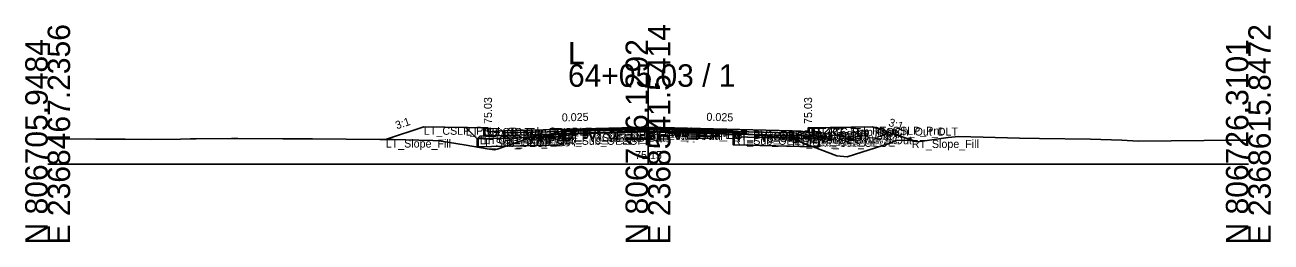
# Model space of a CAD drawing. Extents: x -26 to 8153, y -10 to 9520.
# Drawn here: x 5997.2 to 6152.8, y 4490.3 to 4517.4 of the extents above; entities that cross this region are included whole.
import ezdxf

# ---------------------------------------------------------------- set-up
doc = ezdxf.new("R2010")
doc.units = 0
for name, color, linetype in [('Exist CMT Pavement', 7, 'Continuous'), ('Exist Cross Section Cell', 7, 'Continuous'), ('Exist XS Center Line Elevation Label', 7, 'Continuous'), ('Exist XS Ground Line', 7, 'Continuous'), ('Prop CMT Conc Surface', 7, 'Continuous'), ('Prop CMT Concrete Structures', 7, 'Continuous'), ('Prop CMT Pvmt Course 1', 7, 'Continuous'), ('Prop CMT Pvmt Course 1 CG', 7, 'Continuous'), ('Prop CMT Pvmt Course 1 Wedge', 7, 'Continuous'), ('Prop CMT Pvmt Course 2', 7, 'Continuous'), ('Prop CMT Pvmt Course 2 Wedge', 7, 'Continuous'), ('Prop CMT Pvmt Course 3', 7, 'Continuous'), ('Prop CMT Pvmt Course 3 Wedge', 7, 'Continuous'), ('Prop CMT Pvmt Surface', 7, 'Continuous'), ('Prop CMT Pvmt Wedge Surface 1', 7, 'Continuous'), ('Prop CMT Pvmt Wedge Surface 2', 7, 'Continuous'), ('Prop CMT Pvmt Wedge Surface 3', 7, 'Continuous'), ('Prop CMT Shallow Undercut', 7, 'Continuous'), ('Prop CMT Shallow Undercut Boundary', 7, 'Continuous'), ('Prop CMT Slope Grass', 7, 'Continuous'), ('Prop CMT Subgrade Earthwork', 7, 'Continuous'), ('Prop XS Earthwork Shape', 7, 'Continuous'), ('Prop XS Hydro Elevations', 7, 'Continuous'), ('Prop XS SE Text', 7, 'Continuous'), ('Prop XS Side Slope Text', 7, 'Continuous'), ('Prop XS Subgrade Earthwork', 7, 'Continuous'), ('Scratch_Level_2', 7, 'Continuous'), ('Scratch_Level_6', 7, 'Continuous')]:
    doc.layers.add(name, color=color, linetype=linetype)

msp = doc.modelspace()

# ---------------------------------------------------------------- linework, layer by layer
at = {"layer": 'Exist CMT Pavement'}
for p, q in [((6064.41, 4503.82), (6069.36, 4503.96)), ((6069.36, 4503.96), (6074.69, 4504.16)), ((6074.69, 4504.16), (6075, 4504.15)), ((6075, 4504.15), (6080.34, 4504.06)), ((6080.34, 4504.06), (6085.62, 4503.97))]:
    msp.add_line(p, q, dxfattribs=at)
at = {"layer": 'Exist Cross Section Cell'}
for p, q in [((6075, 4500), (6075, 4512.47)), ((6000, 4500), (6075, 4500)), ((6075, 4500), (6150, 4500))]:
    msp.add_line(p, q, dxfattribs=at)
at = {"layer": 'Exist XS Ground Line'}
for p, q in [((6064.41, 4503.82), (6069.36, 4503.96)), ((6069.36, 4503.96), (6074.69, 4504.16)), ((6074.69, 4504.16), (6075, 4504.15)), ((6075, 4504.15), (6080.34, 4504.06)), ((6080.34, 4504.06), (6085.62, 4503.97)), ((6085.62, 4503.97), (6091.12, 4503.39)), ((6000, 4503.18), (6006, 4503.13)), ((6006, 4503.13), (6009.67, 4503.13)), ((6009.67, 4503.13), (6012.89, 4503.11)), ((6012.89, 4503.11), (6016.59, 4503.15)), ((6016.59, 4503.15), (6017.83, 4503.16)), ((6017.83, 4503.16), (6018.55, 4503.16)), ((6018.55, 4503.16), (6022.98, 4503.21)), ((6022.98, 4503.21), (6023.75, 4503.21)), ((6023.75, 4503.21), (6029.36, 4503.18)), ((6029.36, 4503.18), (6032.63, 4503.17)), ((6032.63, 4503.17), (6033.08, 4503.17)), ((6033.08, 4503.17), (6041.51, 4503.09)), ((6041.51, 4503.09), (6043.17, 4503.08)), ((6043.17, 4503.08), (6046.36, 4503)), ((6046.36, 4503), (6048.13, 4502.95)), ((6048.13, 4502.95), (6048.91, 4502.93)), ((6048.91, 4502.93), (6052.3, 4502.37)), ((6052.3, 4502.37), (6054.91, 4501.94)), ((6056.16, 4501.89), (6060.25, 4503.28)), ((6060.25, 4503.28), (6061.9, 4503.48)), ((6061.9, 4503.48), (6064.41, 4503.82)), ((6091.12, 4503.39), (6092.77, 4503.27)), ((6092.77, 4503.27), (6093.9, 4502.83)), ((6093.9, 4502.83), (6098.6, 4501.07)), ((6099.89, 4500.92), (6105.24, 4502.65)), ((6105.24, 4502.65), (6105.99, 4502.95)), ((6105.99, 4502.95), (6107.52, 4503.03)), ((6107.52, 4503.03), (6108.72, 4502.81)), ((6108.72, 4502.81), (6112.48, 4503.36)), ((6112.48, 4503.36), (6113.83, 4503.45)), ((6113.83, 4503.45), (6121.41, 4503.27)), ((6121.41, 4503.27), (6123.92, 4503.2)), ((6123.92, 4503.2), (6130.28, 4503.13)), ((6130.28, 4503.13), (6134.18, 4503.01)), ((6134.18, 4503.01), (6136.22, 4502.88)), ((6136.22, 4502.88), (6144.46, 4502.96)), ((6144.46, 4502.96), (6147.16, 4502.99)), ((6147.16, 4502.99), (6150, 4503.01)), ((6054.91, 4501.94), (6055.84, 4501.79)), ((6055.84, 4501.79), (6056.16, 4501.89)), ((6098.6, 4501.07), (6099.89, 4500.92))]:
    msp.add_line(p, q, dxfattribs=at)
at = {"layer": 'Prop CMT Conc Surface'}
for points in [[(6055, 4504.03), (6055, 4504.53), (6054.5, 4504.53)], [(6057, 4504.16), (6055, 4504.03)], [(6093, 4504.16), (6095, 4504.03)], [(6095, 4504.03), (6095, 4504.53), (6095.5, 4504.53)]]:
    msp.add_lwpolyline(points, dxfattribs=at)
at = {"layer": 'Prop CMT Concrete Structures'}
for points in [[(6057, 4504.16), (6055, 4504.03), (6055, 4504.53), (6054.5, 4504.53)], [(6054.5, 4504.53), (6054.5, 4503.52), (6057, 4503.58)], [(6057, 4503.58), (6057, 4504.16)], [(6093, 4504.16), (6095, 4504.03), (6095, 4504.53), (6095.5, 4504.53)], [(6095.5, 4504.53), (6095.5, 4503.52), (6093, 4503.58)], [(6093, 4503.58), (6093, 4504.16)]]:
    msp.add_lwpolyline(points, dxfattribs=at)
at = {"layer": 'Prop CMT Pvmt Course 1'}
for points in [[(6075, 4504.61), (6057, 4504.16)], [(6057, 4504.16), (6057, 4503.91)], [(6057, 4503.91), (6064.41, 4504.1)], [(6064.41, 4504.22), (6075, 4504.49)], [(6064.41, 4504.1), (6064.41, 4504.22)], [(6075, 4504.36), (6075, 4504.61)], [(6075, 4504.61), (6093, 4504.16)], [(6075, 4504.36), (6075, 4504.61)], [(6075, 4504.49), (6075, 4504.36), (6075, 4504.36)], [(6085.62, 4504.22), (6075, 4504.49)], [(6075, 4504.49), (6075, 4504.36), (6075, 4504.36)], [(6085.62, 4504.1), (6085.62, 4504.22)], [(6093, 4503.91), (6085.62, 4504.1)], [(6093, 4504.16), (6093, 4503.91)]]:
    msp.add_lwpolyline(points, dxfattribs=at)
at = {"layer": 'Prop CMT Pvmt Course 1 CG'}
for points in [[(6057, 4503.58), (6054, 4503.5), (6053.66, 4503.17)], [(6053.66, 4503.17), (6057, 4503.25)], [(6057, 4503.25), (6057, 4503.58)], [(6093, 4503.58), (6096, 4503.5), (6096.34, 4503.17)], [(6093, 4503.25), (6093, 4503.58)], [(6096.34, 4503.17), (6093, 4503.25)]]:
    msp.add_lwpolyline(points, dxfattribs=at)
at = {"layer": 'Prop CMT Pvmt Course 1 Wedge'}
for points in [[(6075, 4504.49), (6064.41, 4504.22)], [(6075, 4504.49), (6085.62, 4504.22)]]:
    msp.add_lwpolyline(points, dxfattribs=at)
at = {"layer": 'Prop CMT Pvmt Course 2'}
for points in [[(6064.41, 4504.1), (6057, 4503.91)], [(6057, 4503.91), (6057, 4503.58)], [(6064.41, 4503.77), (6064.41, 4504.1)], [(6085.62, 4503.77), (6085.62, 4504.1)], [(6085.62, 4504.1), (6093, 4503.91)], [(6093, 4503.91), (6093, 4503.58)], [(6057, 4503.58), (6064.41, 4503.77)], [(6093, 4503.58), (6085.62, 4503.77)]]:
    msp.add_lwpolyline(points, dxfattribs=at)
at = {"layer": 'Prop CMT Pvmt Course 2 Wedge'}
for points in [[(6075, 4504.36), (6064.41, 4504.1)], [(6075, 4504.36), (6085.62, 4504.1)]]:
    msp.add_lwpolyline(points, dxfattribs=at)
at = {"layer": 'Prop CMT Pvmt Course 3'}
for points in [[(6064.41, 4503.77), (6057, 4503.58)], [(6057, 4503.58), (6057, 4503.25)], [(6057, 4503.25), (6064.41, 4503.43)], [(6064.41, 4503.43), (6064.41, 4503.77)], [(6085.62, 4503.77), (6093, 4503.58)], [(6085.62, 4503.43), (6085.62, 4503.77)], [(6093, 4503.25), (6085.62, 4503.43)], [(6093, 4503.58), (6093, 4503.25)]]:
    msp.add_lwpolyline(points, dxfattribs=at)
at = {"layer": 'Prop CMT Pvmt Course 3 Wedge'}
for points in [[(6075, 4504.03), (6064.41, 4503.77)], [(6075, 4504.03), (6085.62, 4503.77)]]:
    msp.add_lwpolyline(points, dxfattribs=at)
at = {"layer": 'Prop CMT Pvmt Surface'}
for points in [[(6075, 4504.61), (6057, 4504.16)], [(6075, 4504.61), (6093, 4504.16)]]:
    msp.add_lwpolyline(points, dxfattribs=at)
at = {"layer": 'Prop CMT Pvmt Wedge Surface 1'}
for points in [[(6057, 4503.91), (6057, 4504.16)], [(6064.41, 4504.1), (6057, 4503.91)], [(6075, 4504.49), (6064.41, 4504.22)], [(6064.41, 4504.22), (6064.41, 4504.1)], [(6075, 4504.49), (6085.62, 4504.22)], [(6085.62, 4504.22), (6085.62, 4504.1)], [(6085.62, 4504.1), (6093, 4503.91)], [(6093, 4503.91), (6093, 4504.16)]]:
    msp.add_lwpolyline(points, dxfattribs=at)
at = {"layer": 'Prop CMT Pvmt Wedge Surface 2'}
for points in [[(6075, 4504.36), (6057, 4503.91)], [(6057, 4503.91), (6057, 4504.16)], [(6075, 4504.36), (6093, 4503.91)], [(6093, 4503.91), (6093, 4504.16)]]:
    msp.add_lwpolyline(points, dxfattribs=at)
at = {"layer": 'Prop CMT Pvmt Wedge Surface 3'}
for points in [[(6057, 4503.58), (6057, 4504.16)], [(6075, 4504.03), (6057, 4503.58)], [(6075, 4504.03), (6093, 4503.58)], [(6093, 4503.58), (6093, 4504.16)]]:
    msp.add_lwpolyline(points, dxfattribs=at)
at = {"layer": 'Prop CMT Shallow Undercut'}
for points in [[(6060.8, 4503.34), (6064.41, 4503.43), (6064.41, 4502.43), (6057.24, 4502.26), (6060.25, 4503.28)], [(6093.9, 4502.83), (6095.62, 4502.18), (6085.62, 4502.43), (6085.62, 4503.43), (6092.8, 4503.25)]]:
    msp.add_lwpolyline(points, close=True, dxfattribs=at)
at = {"layer": 'Prop CMT Shallow Undercut Boundary'}
for p, q in [((6053.66, 4503.17), (6053.66, 4502.17)), ((6053.66, 4502.17), (6064.41, 4502.43)), ((6064.41, 4503.43), (6064.41, 4502.43)), ((6085.62, 4503.43), (6085.62, 4502.43)), ((6085.62, 4502.43), (6096.34, 4502.17)), ((6096.34, 4503.17), (6096.34, 4502.17))]:
    msp.add_line(p, q, dxfattribs=at)
at = {"layer": 'Prop CMT Slope Grass'}
for points in [[(6054.5, 4504.53), (6047, 4504.68), (6042.21, 4503.09)], [(6095.5, 4504.53), (6103, 4504.68), (6108.52, 4502.84)]]:
    msp.add_lwpolyline(points, dxfattribs=at)
at = {"layer": 'Prop CMT Subgrade Earthwork'}
for points in [[(6057, 4503.25), (6053.66, 4503.17), (6052.25, 4504.58)], [(6085.62, 4503.43), (6085.61, 4503.98)], [(6093, 4503.25), (6096.34, 4503.17), (6097.75, 4504.58)], [(6064.41, 4503.43), (6057, 4503.25)], [(6064.41, 4503.43), (6064.42, 4503.82)], [(6085.62, 4503.43), (6093, 4503.25)]]:
    msp.add_lwpolyline(points, dxfattribs=at)
at = {"layer": 'Prop XS Earthwork Shape'}
for points in [[(6048.13, 4502.95), (6048.91, 4502.93), (6052.3, 4502.37), (6054.91, 4501.94), (6055.84, 4501.79), (6056.16, 4501.89), (6057.24, 4502.26), (6053.66, 4502.17), (6053.66, 4503.17), (6052.25, 4504.58), (6047, 4504.68), (6042.21, 4503.09), (6043.17, 4503.08), (6046.36, 4503)], [(6085.62, 4503.43), (6092.8, 4503.25), (6092.77, 4503.27), (6091.12, 4503.39), (6085.62, 4503.97), (6085.61, 4503.98)], [(6103, 4504.68), (6108.52, 4502.84), (6107.52, 4503.03), (6105.99, 4502.95), (6105.24, 4502.65), (6099.89, 4500.92), (6098.6, 4501.07), (6095.62, 4502.18), (6096.34, 4502.17), (6096.34, 4503.17), (6097.75, 4504.58)], [(6057.24, 4502.26), (6060.25, 4503.28), (6060.8, 4503.34), (6057, 4503.25), (6053.66, 4503.17), (6053.66, 4502.17)], [(6057.24, 4502.26), (6060.25, 4503.28), (6060.8, 4503.34), (6064.41, 4503.43), (6064.41, 4502.43)], [(6064.41, 4503.82), (6064.42, 4503.82), (6064.41, 4503.43), (6060.8, 4503.34), (6061.9, 4503.48)], [(6085.62, 4502.43), (6095.62, 4502.18), (6093.9, 4502.83), (6092.8, 4503.25), (6085.62, 4503.43)], [(6093.9, 4502.83), (6095.62, 4502.18), (6096.34, 4502.17), (6096.34, 4503.17), (6093, 4503.25), (6092.8, 4503.25)]]:
    msp.add_lwpolyline(points, close=True, dxfattribs=at)
at = {"layer": 'Prop XS Subgrade Earthwork'}
for p, q in [((6053.66, 4503.17), (6064.41, 4503.43)), ((6085.62, 4503.43), (6096.34, 4503.17))]:
    msp.add_line(p, q, dxfattribs=at)
at = {"layer": 'Scratch_Level_6'}
for points in [[(6060.8, 4503.34), (6064.41, 4503.43), (6064.41, 4502.43), (6057.24, 4502.26), (6060.25, 4503.28)], [(6093.9, 4502.83), (6095.62, 4502.18), (6085.62, 4502.43), (6085.62, 4503.43), (6092.8, 4503.25)]]:
    msp.add_lwpolyline(points, close=True, dxfattribs=at)

# ---------------------------------------------------------------- texts
at = {"layer": 'Exist Cross Section Cell'}
for s, p in [('E 2368467.2356', (6002.8, 4490)), ('E 2368541.5414', (6077.8, 4490)), ('E 2368615.8472', (6152.8, 4490)), ('N 806705.9484', (6000, 4490)), ('N 806716.1292', (6075, 4490)), ('N 806726.3101', (6150, 4490))]:
    msp.add_text(s, height=2.8, rotation=90, dxfattribs=at).set_placement(p)
for s, p in [('L', (6065, 4512.47)), ('64+05.03 / 1', (6065, 4509.67))]:
    msp.add_text(s, height=2.8, dxfattribs=at).set_placement(p)
at = {"layer": 'Exist XS Center Line Elevation Label'}
msp.add_text('75.15', height=1, dxfattribs=at).set_placement((6073.39, 4500.65))
at = {"layer": 'Prop XS Hydro Elevations'}
for p in [(6055.5, 4505.03), (6095.5, 4505.03)]:
    msp.add_text('75.03', height=1, rotation=90, dxfattribs=at).set_placement(p)
at = {"layer": 'Prop XS SE Text'}
for rotation, p in [(1.4321, (6064.24, 4505.34)), (358.5679, (6082.29, 4505.43))]:
    msp.add_text('0.025', height=1, rotation=rotation, dxfattribs=at).set_placement(p)
at = {"layer": 'Prop XS Side Slope Text'}
for rotation, p in [(18.4349, (6043.62, 4504.35)), (341.565, (6104.96, 4504.82))]:
    msp.add_text('3:1', height=1, rotation=rotation, dxfattribs=at).set_placement(p)
at = {"layer": 'Scratch_Level_2'}
for s, p in [('LT_CSLP_Pnt', (6047, 4503.68)), ('LT_Sub_Trench_Out_DLT', (6052.25, 4503.58)), ('LT_CG_Top_BOC', (6054.5, 4503.53)), ('LT_CG_Top_Face', (6055, 4503.53)), ('LT_CG_Top_Gut', (6055, 4503.03)), ('LT_PV1_OEOT', (6057, 4503.16)), ('LT_PV2_OEOT', (6057, 4502.91)), ('LT_PV1_OEEOP', (6064.41, 4503.22)), ('LT_PV2_OEEOP', (6064.41, 4503.1)), ('LT_PV_Sub_Tie_Out', (6064.42, 4502.82)), ('PV1_PGL', (6075, 4503.61)), ('RT_PV1_IEEOP', (6075, 4503.49)), ('LT_PV1_IEEOP', (6075, 4503.49)), ('RT_PV2_IEEOP', (6075, 4503.36)), ('LT_PV2_IEEOP', (6075, 4503.36)), ('PV2_PGL', (6075, 4503.36)), ('RT_PV_IEEOP_EG', (6075, 4503.15)), ('LT_PV_IEEOP_EG', (6075, 4503.15)), ('RT_PV3_IEEOP', (6075, 4503.03)), ('LT_PV3_IEEOP', (6075, 4503.03)), ('RT_PV_Sub_Tie_Out', (6085.61, 4502.98)), ('RT_PV1_OEEOP', (6085.62, 4503.22)), ('RT_PV2_OEEOP', (6085.62, 4503.1)), ('RT_PV_OEEOP_EG', (6085.62, 4502.97)), ('RT_PV1_OEOT', (6093, 4503.16)), ('RT_PV2_OEOT', (6093, 4502.91)), ('RT_CG_Top_Face', (6095, 4503.53)), ('RT_CG_Top_Gut', (6095, 4503.03)), ('RT_CG_Top_BOC', (6095.5, 4503.53)), ('RT_Sub_Trench_Out_DLT', (6097.75, 4503.58)), ('RT_CSLP_Pnt', (6103, 4503.68)), ('LT_Slope_Fill', (6042.23, 4502.09)), ('LT_Sub_OEOP', (6053.66, 4502.17)), ('LT_CG1_Shelf_Out', (6054, 4502.5)), ('LT_CG_Bot_BOC', (6054.5, 4502.52)), ('LT_PV3_OEOT', (6057, 4502.58)), ('LT_CG_Bot_IE', (6057, 4502.58)), ('LT_Sub_OEOT', (6057, 4502.25)), ('LT_PV_OEEOP_EG', (6064.41, 4502.82)), ('LT_PV3_OEEOP', (6064.41, 4502.77)), ('LT_Sub_OEEOP', (6064.41, 4502.43)), ('RT_PV3_OEEOP', (6085.62, 4502.77)), ('RT_Sub_OEEOP', (6085.62, 4502.43)), ('RT_PV3_OEOT', (6093, 4502.58)), ('RT_CG_Bot_IE', (6093, 4502.58)), ('RT_Sub_OEOT', (6093, 4502.25)), ('RT_CG_Bot_BOC', (6095.5, 4502.52)), ('RT_CG1_Shelf_Out', (6096, 4502.5)), ('RT_Sub_OEOP', (6096.34, 4502.17)), ('RT_Slope_Fill', (6107.94, 4502.04))]:
    msp.add_text(s, height=1, dxfattribs=at).set_placement(p)

doc.saveas('drawing.dxf')
